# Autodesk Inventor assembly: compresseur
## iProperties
Shininess: 41.0
Length Units: 11269
Angle Units: 11279
Time Units: 11290
Mass Units: 11283
Length Display Precision: 3
Angle Display Precision: 2
Created: 2002-11
Part Number: compresseur
Document SubType Name: Assemblage
Designer: poste-2
Density: 0.0
Volumn: 0.0
Area: 0.0
PropertySet Name: Model Information
Control State: 0
Master: False
Checked Out: False
Author: poste-2
